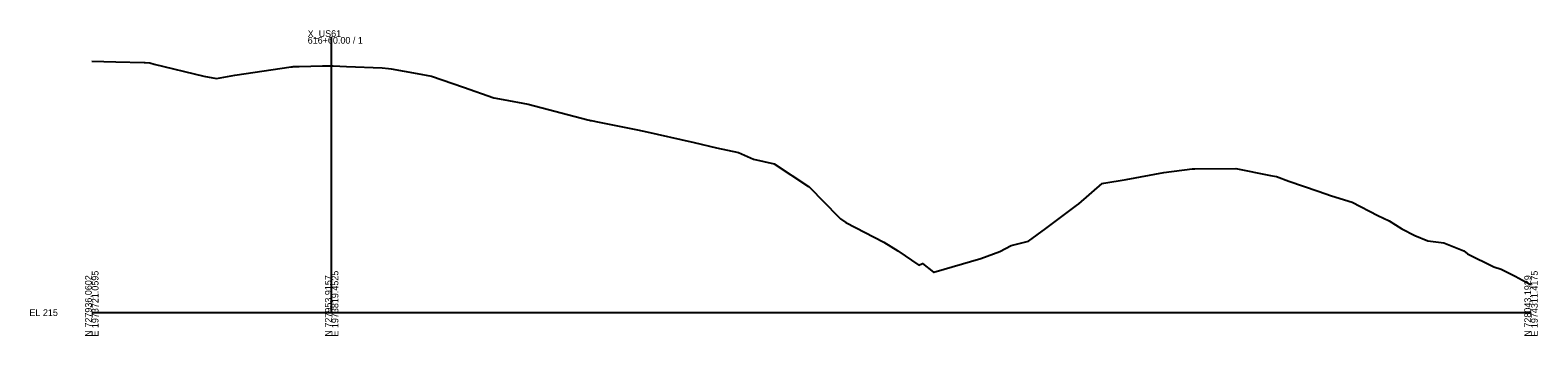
# Model space of a CAD drawing. Extents: x -26 to 1604, y -13 to 9623.
# Drawn here: x 974 to 1603, y 1490 to 1618 of the extents above; entities that cross this region are included whole.
import ezdxf

# ---------------------------------------------------------------- set-up
doc = ezdxf.new("R2010")
doc.units = 0
for name, color, linetype in [('Draft_XS_Grid', 7, 'Continuous'), ('DTM_X_GROUND', 7, 'Continuous'), ('XS_CELL', 7, 'Continuous')]:
    doc.layers.add(name, color=color, linetype=linetype)

msp = doc.modelspace()

# ---------------------------------------------------------------- linework, layer by layer
at = {"layer": 'DTM_X_GROUND'}
msp.add_lwpolyline([(1000, 1604.92), (1009.98, 1604.68), (1021.84, 1604.4), (1022.21, 1604.37), (1024.25, 1604.18), (1026.04, 1603.62), (1046.71, 1598.62), (1051.93, 1597.68), (1059.58, 1598.99), (1083.16, 1602.54), (1083.6, 1602.6), (1083.89, 1602.61), (1086.44, 1602.73), (1096.14, 1602.9), (1100.57, 1602.98), (1106.17, 1602.73), (1121.1, 1602.06), (1123.63, 1601.79), (1124.79, 1601.67), (1135.66, 1599.71), (1141.67, 1598.66), (1154.98, 1594.04), (1167.6, 1589.66), (1171.55, 1588.95), (1181.91, 1586.97), (1206.74, 1580.48), (1207.46, 1580.24), (1207.84, 1580.17), (1208.12, 1580.14), (1211.49, 1579.44), (1226.81, 1576.36), (1230.1, 1575.63), (1251.14, 1571), (1260.44, 1568.79), (1269.6, 1566.73), (1275.85, 1564), (1284.48, 1562.02), (1298.84, 1552.66), (1298.92, 1552.61), (1299, 1552.52), (1299.32, 1552.18), (1311.12, 1540.1), (1312.1, 1539.14), (1314.34, 1537.66), (1330.17, 1529.39), (1336.03, 1525.84), (1344.85, 1519.82), (1346.38, 1520.44), (1350.86, 1516.81), (1350.94, 1516.84), (1350.98, 1516.84), (1370.65, 1522.59), (1378.6, 1525.54), (1383.29, 1527.94), (1390.46, 1529.78), (1397.75, 1535.16), (1410.53, 1544.66), (1411.48, 1545.4), (1421.23, 1553.92), (1421.96, 1554.04), (1431.25, 1555.6), (1446.97, 1558.52), (1458.71, 1559.97), (1459.18, 1560.04), (1459.29, 1560.05), (1459.86, 1560.05), (1476.92, 1560.09), (1491.37, 1557.19), (1493.91, 1556.74), (1499.07, 1554.8), (1511.26, 1550.72), (1516.79, 1548.75), (1525.47, 1546.09), (1536.07, 1540.48), (1540.91, 1538.34), (1546.16, 1534.93), (1551.61, 1532.11), (1557.04, 1529.9), (1563.63, 1529.09), (1572.01, 1525.82), (1573.55, 1524.49), (1584.54, 1519.08), (1587.48, 1518.17), (1593.38, 1515.27), (1599.5, 1511.86), (1600, 1511.68)], dxfattribs=at)
at = {"layer": 'XS_CELL'}
for p, q in [((1100, 1500), (1100, 1615)), ((1000, 1500), (1100, 1500)), ((1100, 1500), (1600, 1500))]:
    msp.add_line(p, q, dxfattribs=at)

# ---------------------------------------------------------------- texts
at = {"layer": 'Draft_XS_Grid'}
msp.add_text('-', height=0.0001, dxfattribs=at).set_placement((1000, 1500))
at = {"layer": 'XS_CELL'}
for s, p in [('X_US61', (1090, 1615)), ('616+60.00 / 1', (1090, 1612.2)), ('EL 215', (974, 1498.6))]:
    msp.add_text(s, height=2.8, dxfattribs=at).set_placement(p)
for s, p in [('N 727936.0602', (1000, 1490)), ('E 1973721.0595', (1002.8, 1490)), ('N 727953.9157', (1100, 1490)), ('E 1973819.4525', (1102.8, 1490)), ('N 728043.1929', (1600, 1490)), ('E 1974311.4175', (1602.8, 1490))]:
    msp.add_text(s, height=2.8, rotation=90, dxfattribs=at).set_placement(p)

doc.saveas('drawing.dxf')
